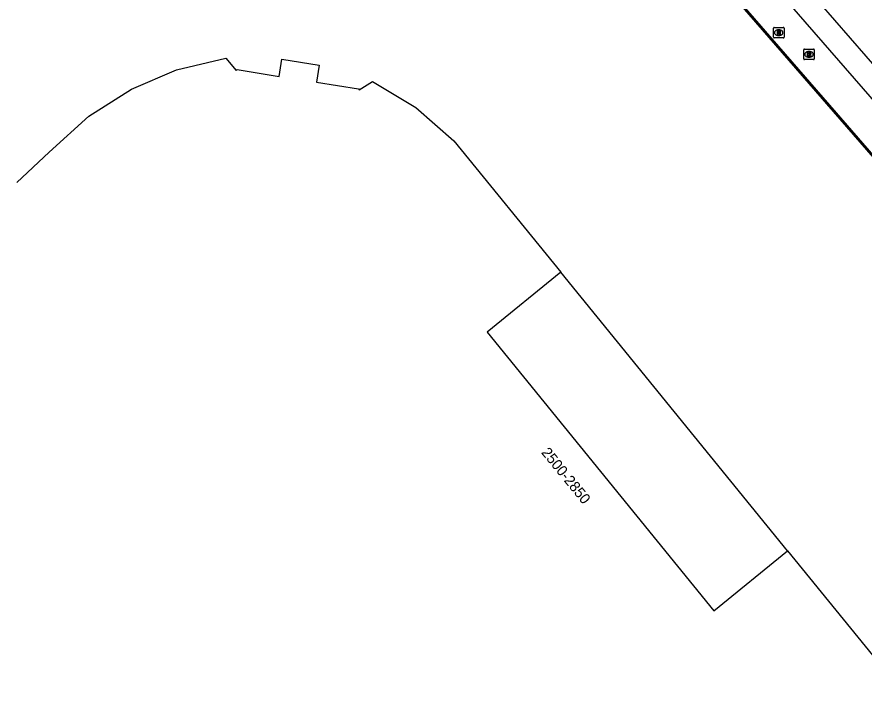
# Model space of a CAD drawing. Extents: x 155018 to 156648, y 383980 to 385733.
# Drawn here: x 156042.7 to 156123, y 384421.7 to 384485.7 of the extents above; entities that cross this region are included whole.
import ezdxf

# ---------------------------------------------------------------- set-up
doc = ezdxf.new("R2010")
doc.units = 0
for name, color, linetype in [('IMGEO_Fietspad_open', 7, 'Continuous'), ('IMGEO_Lijnafwatering', 7, 'Continuous'), ('IMGEO_Pand', 7, 'Continuous'), ('IMGEO_Pand_nummerreeks', 7, 'Continuous'), ('IMGEO_Pand_overbouw', 7, 'Continuous'), ('IMGEO_Rijbaan_lokaal_gesloten', 7, 'Continuous'), ('IMGEO_Rioolput', 7, 'Continuous')]:
    doc.layers.add(name, color=color, linetype=linetype)

msp = doc.modelspace()

# ---------------------------------------------------------------- linework, layer by layer
at = {"layer": 'IMGEO_Fietspad_open'}
msp.add_lwpolyline([(156103.806, 384503.671), (156107.304, 384500), (156112.344, 384494.525), (156112.781, 384494.01), (156141.033, 384461.516)], dxfattribs=at)
at = {"layer": 'IMGEO_Lijnafwatering'}
for points in [[(156106.986, 384492.038), (156107.117, 384491.904), (156119.742, 384477.371)], [(156119.742, 384477.371), (156132.49, 384462.697)]]:
    msp.add_lwpolyline(points, dxfattribs=at)
at = {"layer": 'IMGEO_Pand'}
for points in [[(156042.653, 384470.034), (156045.726, 384472.901), (156049.506, 384476.311), (156053.535, 384478.875), (156057.795, 384480.728), (156062.502, 384481.81), (156063.464, 384480.654), (156063.56, 384480.74), (156067.551, 384480.091), (156067.816, 384481.72), (156071.339, 384481.147), (156071.079, 384479.548), (156075.086, 384478.908), (156075.141, 384478.817), (156076.406, 384479.607), (156080.499, 384477.146), (156084.101, 384473.986), (156094.274, 384461.531)], [(156094.274, 384461.531), (156087.282, 384455.833), (156108.769, 384429.395), (156115.777, 384435.076), (156144.238, 384400.117), (156147.018, 384396.083), (156149.48, 384391.485), (156150.373, 384386.318), (156149.952, 384381.433), (156148.431, 384376.933), (156146.387, 384372.637), (156144.04, 384368.103), (156141.662, 384363.86), (156138.899, 384359.332), (156135.995, 384354.955), (156132.963, 384350.724), (156129.813, 384346.641), (156126.538, 384342.714), (156123.159, 384338.929), (156119.662, 384335.28)]]:
    msp.add_lwpolyline(points, dxfattribs=at)
at = {"layer": 'IMGEO_Pand_overbouw'}
msp.add_lwpolyline([(156115.777, 384435.076), (156094.274, 384461.531), (156087.282, 384455.833), (156108.769, 384429.395)], close=True, dxfattribs=at)
at = {"layer": 'IMGEO_Rijbaan_lokaal_gesloten'}
for points in [[(156102.487, 384496.473), (156107.032, 384491.82), (156179.08, 384408.886)], [(156156.212, 384440.594), (156142.109, 384456.944), (156108.294, 384495.812)]]:
    msp.add_lwpolyline(points, dxfattribs=at)
at = {"layer": 'IMGEO_Rioolput'}
for p, q in [((156114.431, 384483.811), (156114.431, 384484.663)), ((156114.506, 384484.737), (156115.358, 384484.737)), ((156114.919, 384484.517), (156114.944, 384484.517)), ((156115.432, 384484.663), (156115.432, 384483.811)), ((156115.358, 384483.737), (156114.506, 384483.737)), ((156114.942, 384483.957), (156114.917, 384483.957)), ((156117.305, 384481.761), (156117.305, 384482.613)), ((156117.38, 384482.687), (156118.232, 384482.687)), ((156117.793, 384482.467), (156117.818, 384482.467)), ((156118.306, 384482.613), (156118.306, 384481.761)), ((156118.232, 384481.687), (156117.38, 384481.687)), ((156117.816, 384481.907), (156117.791, 384481.907))]:
    msp.add_line(p, q, dxfattribs=at)
for points in [[(156114.431, 384483.811), (156114.431, 384484.663)], [(156114.506, 384484.737), (156115.358, 384484.737)], [(156115.02, 384484.435), (156114.768, 384484.437), (156114.768, 384484.037)], [(156114.946, 384484.356), (156114.892, 384484.356), (156114.892, 384484.275)], [(156115.432, 384484.663), (156115.432, 384483.811)], [(156115.358, 384483.737), (156114.506, 384483.737)], [(156114.768, 384484.037), (156114.892, 384484.037), (156114.892, 384484.199), (156114.903, 384484.199)], [(156114.892, 384484.275), (156114.944, 384484.275)], [(156114.95, 384484.17), (156115.021, 384484.037), (156115.161, 384484.037), (156115.096, 384484.163)], [(156117.305, 384481.761), (156117.305, 384482.613)], [(156117.38, 384482.687), (156118.232, 384482.687)], [(156117.894, 384482.385), (156117.642, 384482.387), (156117.642, 384481.987)], [(156117.642, 384481.987), (156117.766, 384481.987), (156117.766, 384482.149), (156117.777, 384482.149)], [(156117.82, 384482.306), (156117.766, 384482.306), (156117.766, 384482.225)], [(156117.766, 384482.225), (156117.818, 384482.225)], [(156117.824, 384482.12), (156117.895, 384481.987), (156118.035, 384481.987), (156117.97, 384482.113)], [(156118.306, 384482.613), (156118.306, 384481.761)], [(156118.232, 384481.687), (156117.38, 384481.687)]]:
    msp.add_lwpolyline(points, dxfattribs=at)
for centre, radius, start, end in [((156114.508, 384484.661), 0.0765, 91.55205, 178.44795), ((156114.508, 384484.661), 0.0765, 91.55205, 178.44795), ((156114.952, 384484.26), 0.0964, 77.00612, 93.18647), ((156114.966, 384484.317), 0.0378, 276.66336, 79.67722), ((156115.019, 384484.325), 0.109, 350.36119, 89.41601), ((156115.356, 384484.661), 0.0765, 1.55205, 88.44795), ((156115.356, 384484.661), 0.0765, 1.55205, 88.44795), ((156114.508, 384483.813), 0.0765, 181.55205, 268.44795), ((156114.508, 384483.813), 0.0765, 181.55205, 268.44795), ((156114.902, 384484.146), 0.0533, 26.02933, 88.69889), ((156114.928, 384484.464), 0.19, 274.7715, 282.96867), ((156115.017, 384484.325), 0.112, 277.58423, 350.98172), ((156115.001, 384484.11), 0.108, 29.51342, 73.79051), ((156115.356, 384483.813), 0.0765, 271.55205, 358.44795), ((156115.356, 384483.813), 0.0765, 271.55205, 358.44795), ((156117.382, 384482.611), 0.0765, 91.55205, 178.44795), ((156117.382, 384482.611), 0.0765, 91.55205, 178.44795), ((156117.776, 384482.096), 0.0533, 26.02933, 88.69889), ((156117.802, 384482.414), 0.19, 274.7715, 282.96867), ((156117.826, 384482.21), 0.0964, 77.00612, 93.18647), ((156117.84, 384482.267), 0.0378, 276.66336, 79.67722), ((156117.893, 384482.275), 0.109, 350.36119, 89.41601), ((156117.891, 384482.275), 0.112, 277.58423, 350.98172), ((156117.875, 384482.06), 0.108, 29.51342, 73.79051), ((156118.23, 384482.611), 0.0765, 1.55205, 88.44795), ((156118.23, 384482.611), 0.0765, 1.55205, 88.44795), ((156117.382, 384481.763), 0.0765, 181.55205, 268.44795), ((156117.382, 384481.763), 0.0765, 181.55205, 268.44795), ((156118.23, 384481.763), 0.0765, 271.55205, 358.44795), ((156118.23, 384481.763), 0.0765, 271.55205, 358.44795)]:
    msp.add_arc(centre, radius, start, end, dxfattribs=at)
for centre, major_axis, ratio, start_param, end_param in [((156114.918, 384484.237), (-0.387, 0.002), 0.722429, 4.712389, 7.853982), ((156114.943, 384484.237), (-0.39, 0.002), 0.717154, 1.570796, 4.712389), ((156117.792, 384482.187), (-0.387, 0.002), 0.722429, 4.712389, 7.853982), ((156117.817, 384482.187), (-0.39, 0.002), 0.717154, 1.570796, 4.712389)]:
    msp.add_ellipse(centre, major_axis=major_axis, ratio=ratio, start_param=start_param, end_param=end_param, dxfattribs=at)

# ---------------------------------------------------------------- texts
at = {"layer": 'IMGEO_Pand_nummerreeks'}
msp.add_text('2500-2850', height=1, rotation=309.10185, dxfattribs=at).set_placement((156092.358, 384444.386))

doc.saveas('drawing.dxf')
